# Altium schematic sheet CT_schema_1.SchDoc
size 387 x 258 mm
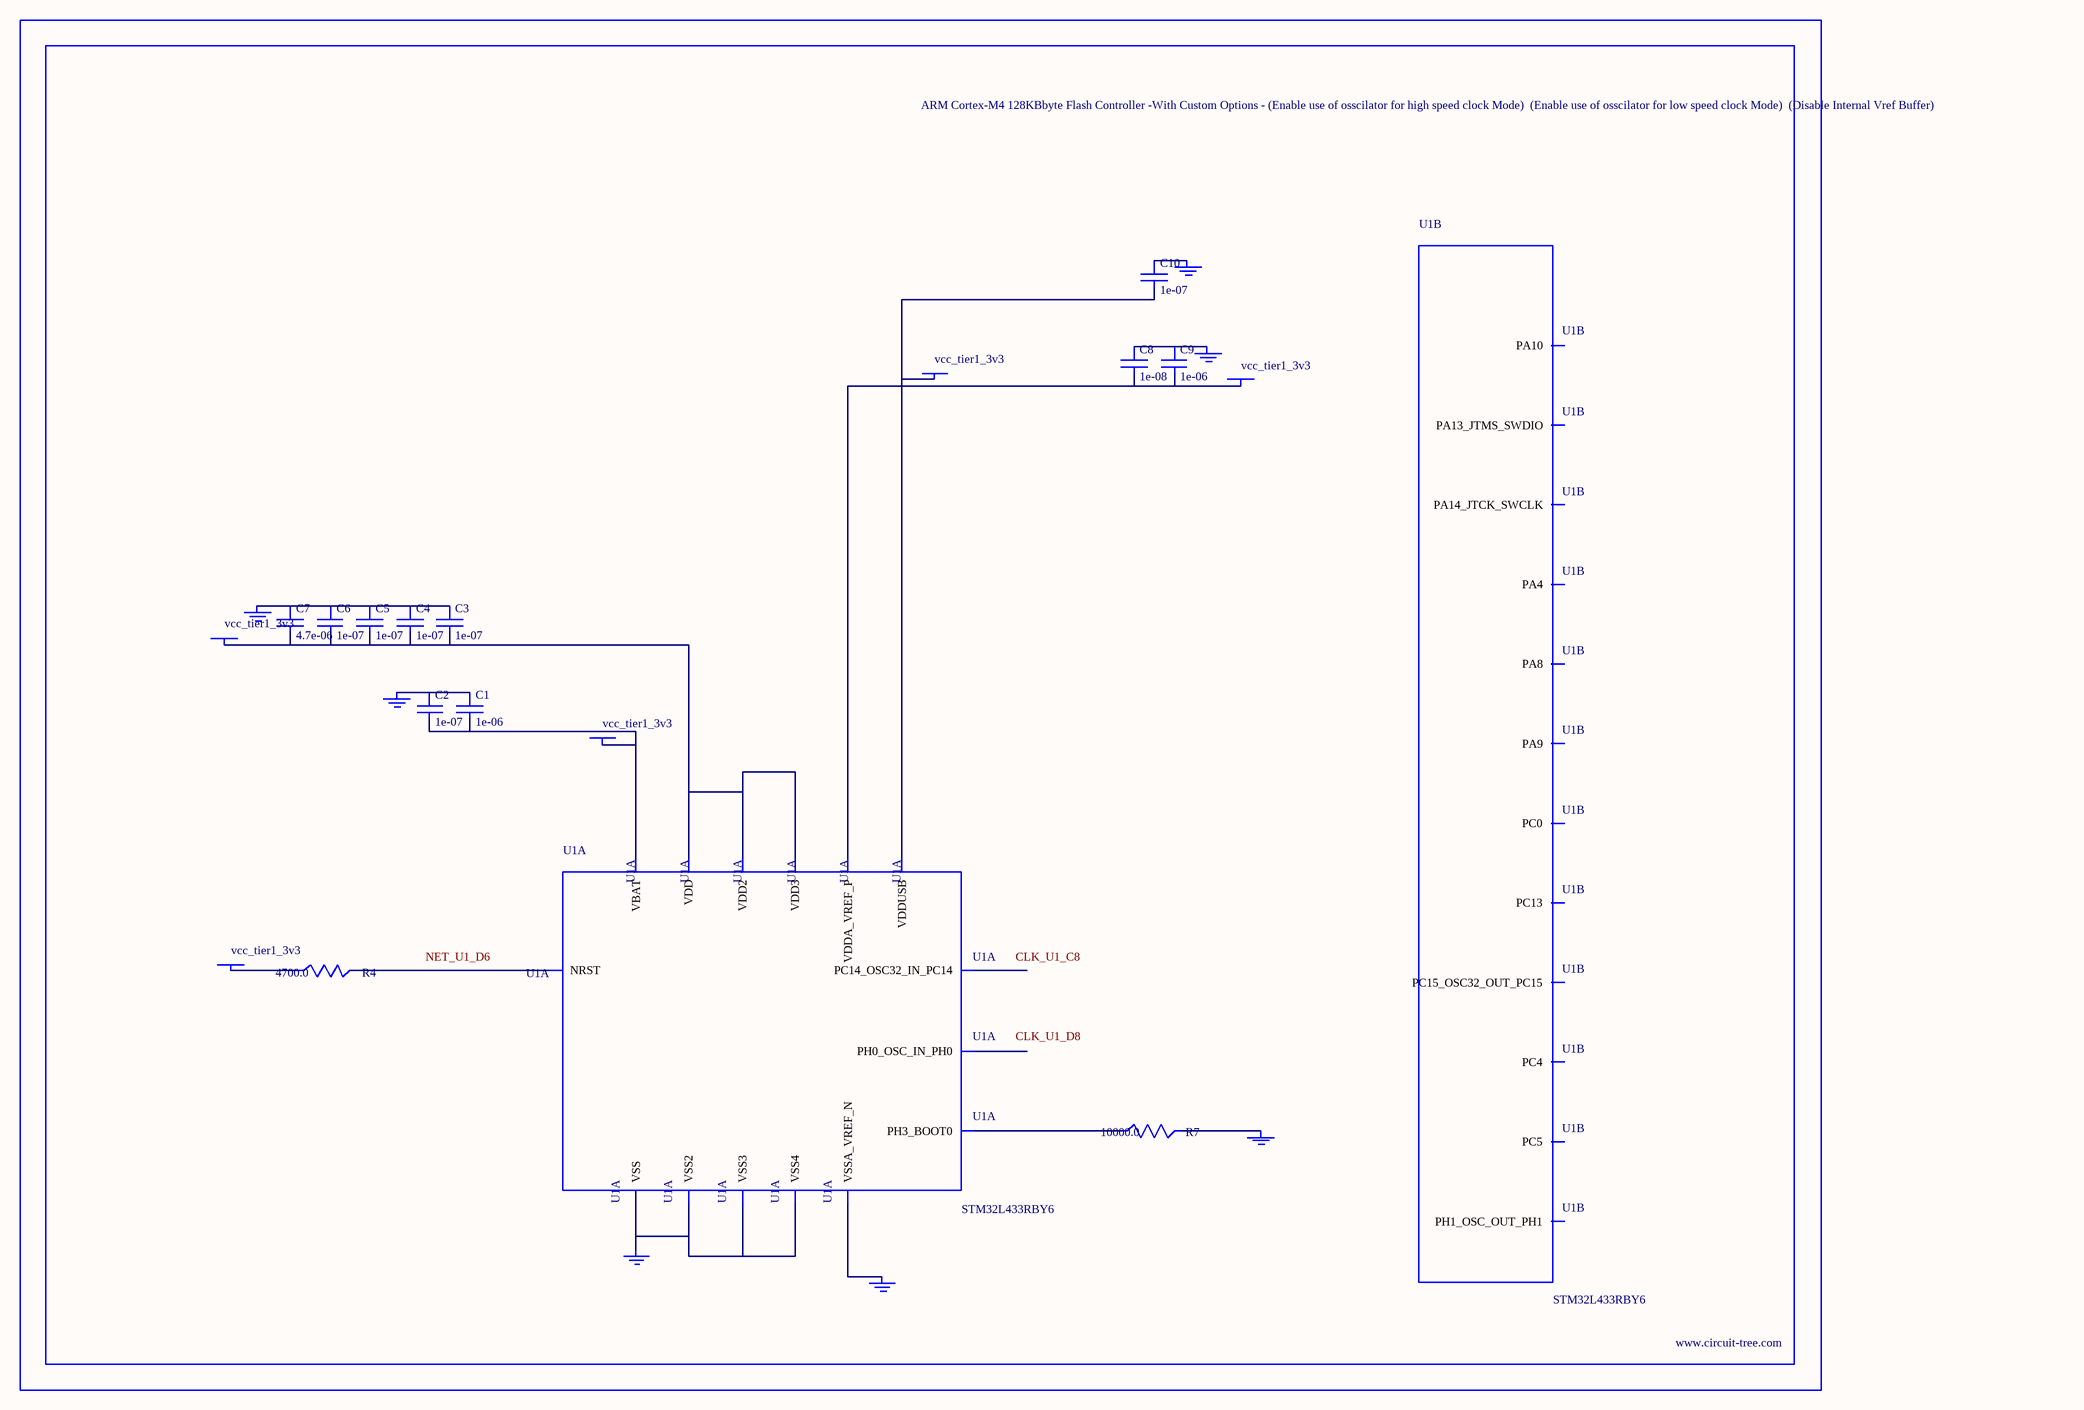
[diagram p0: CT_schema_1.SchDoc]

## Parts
BORDER0  (no value)
C1  1e-06  [C0603]
C2  1e-07  [C0603]
C3  1e-07  [C0603]
C4  1e-07  [C0603]
C5  1e-07  [C0603]
C6  1e-07  [C0603]
C7  4.7e-06  [C0603]
C8  1e-08  [C0603]
C9  1e-06  [C0603]
C10  1e-07  [C0603]
GND_INSTANCE_0_0  (no value)
GND_INSTANCE_0_1  (no value)
GND_INSTANCE_0_2  (no value)
GND_INSTANCE_0_3  (no value)
GND_INSTANCE_0_4  (no value)
GND_INSTANCE_0_5  (no value)
GND_INSTANCE_0_6  (no value)
POWER_INSTANCE_0_0  vcc_tier1_3v3
POWER_INSTANCE_0_1  vcc_tier1_3v3
POWER_INSTANCE_0_2  vcc_tier1_3v3
POWER_INSTANCE_0_3  vcc_tier1_3v3
POWER_INSTANCE_0_4  vcc_tier1_3v3
R4  4700.0  [R0603]
R7  10000.0  [R0603]
U1  STM32L433RBY6  [WLCSP64]  (parts A,B of 6)

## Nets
NetC1_1: C1.1 C2.1 GND_INSTANCE_0_0.0(GND)
NetC1_2: C1.2 C2.2 POWER_INSTANCE_0_0.0(PWR) U1.B7(VBAT)
NetC3_1: C3.1 C4.1 C5.1 C6.1 C7.1 GND_INSTANCE_0_1.0(GND)
NetC3_2: C3.2 C4.2 C5.2 C6.2 C7.2 POWER_INSTANCE_0_1.0(PWR) U1.A8(VDD) U1.H1(VDD2) U1.H7(VDD3)
NetC8_1: C8.1 C9.1 GND_INSTANCE_0_3.0(GND)
NetC8_2: C8.2 C9.2 POWER_INSTANCE_0_2.0(PWR) U1.G8(VDDA_VREF_P)
NetC10_1: C10.1 GND_INSTANCE_0_4.0(GND)
NetC10_2: C10.2 POWER_INSTANCE_0_3.0(PWR) U1.A1(VDDUSB)
NetGND_INSTANCE_0_2_0: GND_INSTANCE_0_2.0(GND) R7.2
NetGND_INSTANCE_0_5_0: GND_INSTANCE_0_5.0(GND) U1.F8(VSSA_VREF_N)
NetGND_INSTANCE_0_6_0: GND_INSTANCE_0_6.0(GND) U1.A7(VSS) U1.B1(VSS2) U1.H2(VSS3) U1.H8(VSS4)
NetPOWER_INSTANCE_0_4_0: POWER_INSTANCE_0_4.0(PWR) R4.1
NetR4_2: R4.2 U1.D6(NRST)
NetR7_1: R7.1 U1.C5(PH3_BOOT0)

Not connected (* = marked no-connect by the designer): U1 B2(PA14_JTCK_SWCLK) B8(PC13) C2(PA13_JTMS_SWDIO) C7(PC15_OSC32_OUT_PC15) C8(PC14_OSC32_IN_PC14) D1(PA9) D2(PA10) D4(PC4) D5(PC0) D7(PH1_OSC_OUT_PH1) D8(PH0_OSC_IN_PH0) E3(PA8) E4(PC5) E5(PA4)

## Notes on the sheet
- Labels drawn without touching a wire or pin: CLK_U1_C8, CLK_U1_D8, NET_U1_D6

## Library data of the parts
BORDER0 = BORDER_PAGE0
C1 C9 = C0603C105K3RACTU
C2-C6 C10 = 06035C104K4Z2A
C7 = GRM188R6YA475KE15D
C8 = 06035C103K4Z2A
GND_INSTANCE_0_0-GND_INSTANCE_0_6 = GND
POWER_INSTANCE_0_0-POWER_INSTANCE_0_4 = PWR
R4 = RC0603JR-074K7L
R7 = RC0603JR-0710KL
